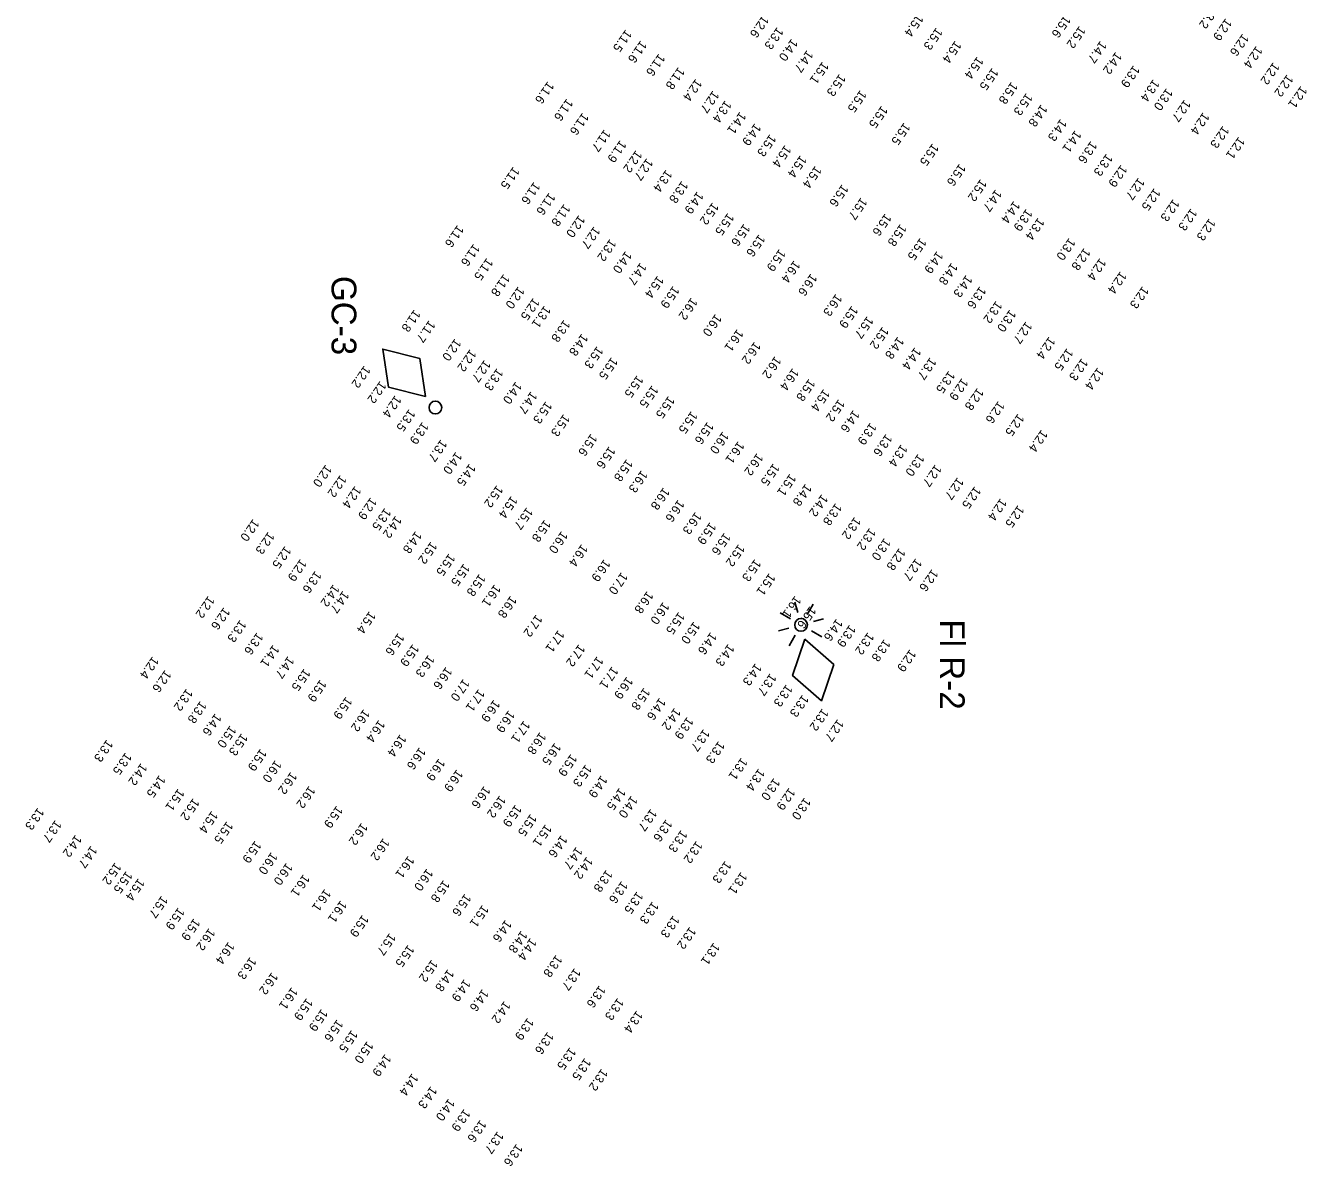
# Model space of a CAD drawing. Extents: x 815385 to 820851, y 582449 to 604245.
# Drawn here: x 815385 to 816108, y 582449 to 583093 of the extents above; entities that cross this region are included whole.
import ezdxf

# ---------------------------------------------------------------- set-up
doc = ezdxf.new("R2010")
doc.units = 0
for name, color, linetype in [('V-CHAN-AIDS', 7, 'Continuous'), ('V-TOPO-SOUN-101408', 7, 'Continuous'), ('V-TOPO-SOUN-EXCSS', 7, 'Continuous')]:
    doc.layers.add(name, color=color, linetype=linetype)

msp = doc.modelspace()

# ---------------------------------------------------------------- linework, layer by layer
at = {"layer": 'V-CHAN-AIDS'}
for p, q in [((815820.52, 582762.05), (815818.96, 582767.85)), ((815829.17, 582766.86), (815825.77, 582760.98)), ((815810.62, 582761.89), (815816.5, 582758.49)), ((815829.33, 582756.96), (815835.13, 582758.52)), ((815815.43, 582753.24), (815809.63, 582751.68)), ((815818.99, 582749.22), (815815.59, 582743.34)), ((815828.26, 582751.71), (815834.14, 582748.31))]:
    msp.add_line(p, q, dxfattribs=at)
for points in [[(815610.36, 582884.04), (815607.23, 582905.45), (815586.27, 582910.8), (815589.4, 582889.39)], [(815824.55, 582746.99), (815817.62, 582726.49), (815833.87, 582712.21), (815840.8, 582732.71)]]:
    msp.add_lwpolyline(points, close=True, dxfattribs=at)
for centre in [(815615.98, 582877.8), (815822.38, 582755.1)]:
    msp.add_circle(centre, 3.6, dxfattribs=at)

# ---------------------------------------------------------------- texts
for s, p in [('GC-3', (815557.34, 582952.11)), ('Fl R-2', (815900.75, 582758.18))]:
    msp.add_text(s, height=14, rotation=270, dxfattribs=at).set_placement(p)
at = {"layer": 'V-TOPO-SOUN-101408'}
for s, p in [('13.2 ', (816054.23, 583104.6)), ('12.6 ', (815800.69, 583099.47)), ('15.4 ', (815887.89, 583100.1)), ('15.6 ', (815971.04, 583099.51)), ('12.9 ', (816062.08, 583097.84)), ('11.5 ', (815723.37, 583091.48)), ('13.3 ', (815808.89, 583092.87)), ('15.3 ', (815898.72, 583092.62)), ('15.2 ', (815979.46, 583093.52)), ('12.6 ', (816071.65, 583089.16)), ('11.6 ', (815731.82, 583085.31)), ('14.0 ', (815817.01, 583086.34)), ('15.4 ', (815909.36, 583085.17)), ('14.7 ', (815991.35, 583085.14)), ('12.4 ', (816079.35, 583082.25)), ('11.6 ', (815742.07, 583077.88)), ('14.7 ', (815825.73, 583079.86)), ('15.4 ', (815921.83, 583076.27)), ('14.2 ', (816000, 583078.92)), ('11.8 ', (815753.14, 583070.29)), ('15.1 ', (815834.48, 583073.42)), ('15.3 ', (815844.04, 583066.43)), ('15.5 ', (815930.27, 583069.86)), ('13.9 ', (816010.07, 583071.31)), ('12.2 ', (816088.97, 583073.04)), ('11.6 ', (815679.4, 583062.22)), ('12.4 ', (815762.92, 583063.72)), ('15.8 ', (815941.12, 583061.99)), ('13.4 ', (816021.22, 583063.42)), ('12.2 ', (816096.73, 583066.15)), ('12.1 ', (816104.56, 583059.7)), ('11.6 ', (815690.13, 583052.51)), ('12.7 ', (815772.62, 583057.03)), ('15.5 ', (815855.8, 583057.36)), ('15.3 ', (815949.55, 583055.62)), ('13.0 ', (816028.67, 583058.4)), ('12.7 ', (816038.83, 583051.97)), ('13.4 ', (815779.59, 583051.54)), ('14.1 ', (815787.85, 583045.07)), ('15.5 ', (815867.8, 583048.47)), ('14.8 ', (815957.93, 583049.21)), ('12.4 ', (816049.4, 583044.8)), ('11.6 ', (815699.02, 583044.55)), ('14.9 ', (815796.29, 583038.57)), ('15.5 ', (815880.51, 583038.96)), ('14.3 ', (815968.87, 583041.06)), ('11.7 ', (815711.32, 583035.13)), ('15.3 ', (815804.78, 583032.39)), ('14.1 ', (815977.09, 583034.67)), ('12.3 ', (816060.53, 583037.14)), ('12.1 ', (816069.43, 583030.98)), ('11.9 ', (815720.23, 583029.03)), ('12.2 ', (815729.16, 583023.35)), ('15.4 ', (815813.29, 583026.27)), ('15.5 ', (815896.58, 583027.21)), ('13.6 ', (815985.96, 583028.55)), ('12.7 ', (815735.27, 583018.87)), ('15.4 ', (815821.99, 583020.52)), ('15.6 ', (815911.83, 583015.8)), ('13.3 ', (815994.75, 583021.4)), ('11.5 ', (815659.93, 583014.05)), ('13.4 ', (815746.14, 583012.37)), ('15.4 ', (815830.43, 583014.57)), ('12.9 ', (816002.99, 583015.15)), ('11.6 ', (815671.62, 583005.49)), ('13.8 ', (815755.08, 583006.08)), ('15.6 ', (815845.56, 583004.09)), ('15.2 ', (815923.7, 583007.08)), ('14.7 ', (815932.19, 583001.25)), ('12.7 ', (816012.82, 583007.88)), ('12.5 ', (816021.75, 583001.94)), ('11.6 ', (815680.14, 582999.38)), ('14.9 ', (815763.76, 583000.06)), ('15.7 ', (815856.23, 582996.66)), ('14.4 ', (815942.48, 582994.74)), ('12.3 ', (816032.46, 582995.8)), ('11.8 ', (815688.6, 582993.02)), ('12.0 ', (815696.93, 582986.73)), ('15.2 ', (815772.4, 582993.89)), ('15.5 ', (815781.02, 582987.92)), ('15.6 ', (815869.87, 582987.64)), ('13.9 ', (815949.5, 582990.27)), ('12.3 ', (816042.49, 582990.56)), ('11.6 ', (815628.46, 582981.17)), ('12.7 ', (815705.49, 582980.36)), ('15.6 ', (815790.12, 582981.84)), ('15.8 ', (815878.41, 582981.75)), ('13.4 ', (815956.22, 582985.29)), ('12.3 ', (816052.83, 582984.92)), ('13.2 ', (815714.52, 582973.29)), ('15.6 ', (815798.61, 582975.88)), ('15.5 ', (815889.66, 582973.88)), ('13.0 ', (815973.69, 582973.83)), ('11.6 ', (815637.55, 582970.53)), ('14.0 ', (815723.31, 582966.47)), ('15.9 ', (815810.11, 582967.58)), ('14.9 ', (815899.1, 582966.4)), ('12.8 ', (815982.2, 582968.19)), ('11.5 ', (815644.96, 582962.52)), ('14.7 ', (815731.64, 582959.93)), ('16.4 ', (815818.41, 582961.15)), ('14.8 ', (815907.3, 582959.87)), ('12.4 ', (815991.07, 582962.47)), ('11.8 ', (815654.5, 582953.45)), ('15.4 ', (815741.37, 582952.53)), ('16.6 ', (815827.91, 582953.74)), ('14.3 ', (815915.55, 582952.92)), ('12.4 ', (816002.64, 582954.97)), ('12.0 ', (815662.73, 582946.46)), ('15.9 ', (815750.16, 582946.76)), ('13.6 ', (815923.31, 582946.54)), ('12.3 ', (816015.16, 582946.58)), ('12.5 ', (815671.26, 582940.04)), ('16.2 ', (815760.39, 582940.15)), ('16.3 ', (815842.04, 582942.28)), ('13.2 ', (815932.45, 582938.3)), ('11.8 ', (815604.02, 582933.4)), ('13.1 ', (815677.52, 582935.66)), ('16.0 ', (815774.04, 582930.9)), ('15.9 ', (815851, 582935.51)), ('15.7 ', (815859.7, 582929.65)), ('13.0 ', (815940.2, 582933.39)), ('11.7 ', (815612.38, 582927.37)), ('13.8 ', (815688.52, 582927.62)), ('16.1 ', (815786.32, 582922.36)), ('15.2 ', (815868.37, 582923.71)), ('12.7 ', (815949.34, 582926.69)), ('12.0 ', (815627, 582917.03)), ('14.8 ', (815698.61, 582919.85)), ('16.2 ', (815796.1, 582915.29)), ('14.8 ', (815876.96, 582918.09)), ('12.4 ', (815962.37, 582918.11)), ('12.2 ', (815635.51, 582910.99)), ('15.3 ', (815707.21, 582912.72)), ('14.4 ', (815886.58, 582912.07)), ('12.5 ', (815972.51, 582911.58)), ('12.2 ', (815575.79, 582901.78)), ('12.7 ', (815643.63, 582904.98)), ('13.3 ', (815650.73, 582900.28)), ('15.5 ', (815715.36, 582906.53)), ('16.2 ', (815807.68, 582907.08)), ('16.4 ', (815817.64, 582900.34)), ('13.7 ', (815895.22, 582906.39)), ('12.3 ', (815980.83, 582905.93)), ('12.4 ', (815989.82, 582900.72)), ('12.2 ', (815584.72, 582893.06)), ('15.5 ', (815729.84, 582896.32)), ('15.8 ', (815826.82, 582894.28)), ('13.5 ', (815905.75, 582898.8)), ('12.9 ', (815913.19, 582894.7)), ('14.0 ', (815661.28, 582892.7)), ('14.7 ', (815669.92, 582887.23)), ('15.5 ', (815738.27, 582890.61)), ('15.4 ', (815835.13, 582888.52)), ('12.8 ', (815921.94, 582889.17)), ('12.4 ', (815593.24, 582885.02)), ('15.3 ', (815678.31, 582881.61)), ('15.5 ', (815747.53, 582884.59)), ('15.2 ', (815843.56, 582882.76)), ('12.6 ', (815933.74, 582881.72)), ('13.5 ', (815601.1, 582877.19)), ('15.3 ', (815688.34, 582874.39)), ('15.5 ', (815760.41, 582876.02)), ('14.6 ', (815851.87, 582876.66)), ('12.5 ', (815944.82, 582874.59)), ('13.9 ', (815608.6, 582869.93)), ('15.6 ', (815769.52, 582869.99)), ('16.0 ', (815778.14, 582864.52)), ('13.9 ', (815861.46, 582869.56)), ('12.4 ', (815958.07, 582865.57)), ('13.7 ', (815619.04, 582860.07)), ('15.6 ', (815703.78, 582863.3)), ('16.1 ', (815786.87, 582859.07)), ('13.6 ', (815870.34, 582863.18)), ('13.4 ', (815878.94, 582857.33)), ('14.0 ', (815627.5, 582853.07)), ('15.6 ', (815714.04, 582856.16)), ('16.2 ', (815797.5, 582852.32)), ('13.0 ', (815888.45, 582851.92)), ('12.0 ', (815554.01, 582845.84)), ('14.5 ', (815635.18, 582846.44)), ('15.8 ', (815723.89, 582848.95)), ('16.3 ', (815732.22, 582842.66)), ('15.5 ', (815806.72, 582846.58)), ('12.7 ', (815898.16, 582845.94)), ('12.2 ', (815562.27, 582840.05)), ('15.1 ', (815816.06, 582840.68)), ('14.8 ', (815824.86, 582835.04)), ('12.7 ', (815910.69, 582838.65)), ('12.4 ', (815570.57, 582833.83)), ('15.2 ', (815650.62, 582834.24)), ('15.4 ', (815658.8, 582828.19)), ('16.8 ', (815744.68, 582832.94)), ('14.2 ', (815834.05, 582829.15)), ('12.5 ', (815920.42, 582833.63)), ('12.9 ', (815579.4, 582827.39)), ('13.5 ', (815587.38, 582821.36)), ('15.7 ', (815667.5, 582821.74)), ('16.6 ', (815753, 582826.08)), ('13.8 ', (815841.88, 582824.11)), ('12.4 ', (815935, 582826.86)), ('12.5 ', (815944.85, 582822.97)), ('12.0 ', (815513.01, 582815.19)), ('14.2 ', (815593.45, 582816.97)), ('15.8 ', (815677.58, 582814.78)), ('16.3 ', (815762.72, 582819.11)), ('15.9 ', (815770.93, 582813.32)), ('13.2 ', (815852.6, 582816.33)), ('12.3 ', (815521.59, 582807.92)), ('14.8 ', (815604.76, 582808.32)), ('16.0 ', (815687.17, 582808.34)), ('15.6 ', (815779.08, 582807.4)), ('13.2 ', (815861.07, 582810.11)), ('12.5 ', (815531.03, 582799.88)), ('15.2 ', (815613.41, 582802.39)), ('16.4 ', (815698.48, 582800.94)), ('15.2 ', (815787.1, 582800.92)), ('13.0 ', (815869.4, 582804.36)), ('12.8 ', (815877.79, 582798.77)), ('12.9 ', (815539.73, 582792.57)), ('15.5 ', (815623.6, 582795.66)), ('16.9 ', (815711.19, 582792.45)), ('15.3 ', (815796.25, 582792.51)), ('12.7 ', (815887.11, 582792.94)), ('13.6 ', (815548.14, 582785.9)), ('15.5 ', (815631.93, 582789.96)), ('17.0 ', (815720.96, 582785.13)), ('15.1 ', (815804.39, 582784.59)), ('12.6 ', (815896.28, 582786.85)), ('14.2 ', (815558.31, 582778.26)), ('15.8 ', (815640.75, 582784.17)), ('16.1 ', (815649.34, 582778.23)), ('12.2 ', (815487.76, 582771.79)), ('14.7 ', (815563.74, 582774.63)), ('16.8 ', (815658.37, 582771.83)), ('16.8 ', (815735.47, 582774.42)), ('12.6 ', (815496.51, 582765.25)), ('15.4 ', (815578.7, 582763.11)), ('16.0 ', (815744.5, 582768.27)), ('15.5 ', (815753.29, 582762.68)), ('13.3 ', (815505.68, 582758.19)), ('17.2 ', (815672.84, 582761.23)), ('15.0 ', (815761.83, 582757.27)), ('14.6 ', (815842.37, 582758.88)), ('13.9 ', (815849.76, 582755.43)), ('13.6 ', (815515.23, 582751.11)), ('15.6 ', (815594.91, 582750.75)), ('17.1 ', (815685.29, 582752.48)), ('14.6 ', (815771.32, 582751.25)), ('13.2 ', (815860.05, 582751.12)), ('14.1 ', (815524.32, 582744.16)), ('15.9 ', (815603.18, 582744.52)), ('17.2 ', (815696.92, 582744.45)), ('14.3 ', (815781.25, 582744.64)), ('13.8 ', (815869.33, 582747.27)), ('12.9 ', (815883.77, 582741.52)), ('12.4 ', (815456.3, 582737.58)), ('14.7 ', (815532.73, 582737.7)), ('16.3 ', (815611.96, 582738.45)), ('17.1 ', (815707.26, 582737.66)), ('14.3 ', (815796.6, 582733.71)), ('12.6 ', (815463.34, 582729.94)), ('15.5 ', (815541.87, 582730.7)), ('16.6 ', (815621.92, 582731.66)), ('17.1 ', (815715.69, 582731.91)), ('13.7 ', (815804.94, 582728.01)), ('13.2 ', (815475.45, 582719.41)), ('15.9 ', (815550.94, 582724.51)), ('17.0 ', (815631.74, 582724.92)), ('16.9 ', (815723.98, 582726.12)), ('15.8 ', (815733.68, 582719.9)), ('13.3 ', (815814.07, 582721.77)), ('13.8 ', (815483.23, 582712.4)), ('15.9 ', (815565.48, 582714.79)), ('17.1 ', (815640.29, 582719.1)), ('16.9 ', (815648.91, 582713.13)), ('14.6 ', (815742.5, 582714.23)), ('13.3 ', (815823.19, 582715.97)), ('14.6 ', (815491.66, 582705.4)), ('16.2 ', (815575.46, 582707.77)), ('16.9 ', (815657.3, 582707.15)), ('14.2 ', (815750.94, 582708.54)), ('13.2 ', (815834.38, 582708.16)), ('15.0 ', (815500.03, 582698.54)), ('16.4 ', (815583.99, 582701.71)), ('17.1 ', (815665.88, 582701.34)), ('13.9 ', (815758.1, 582703.42)), ('12.7 ', (815843.02, 582702.13)), ('13.3 ', (815430.43, 582690.63)), ('15.3 ', (815506.52, 582694.14)), ('16.4 ', (815596.05, 582693.58)), ('16.8 ', (815674.97, 582694.84)), ('13.7 ', (815767.32, 582696.56)), ('13.5 ', (815440.99, 582683.32)), ('15.9 ', (815517.18, 582685.46)), ('16.6 ', (815606.99, 582686.29)), ('16.5 ', (815683.34, 582688.82)), ('13.3 ', (815775.8, 582689.77)), ('14.2 ', (815449.76, 582677.32)), ('16.0 ', (815525.57, 582678.99)), ('16.9 ', (815617.89, 582679.94)), ('15.9 ', (815692.41, 582682.46)), ('15.3 ', (815700.75, 582676.55)), ('13.1 ', (815788.64, 582680.42)), ('14.5 ', (815460.07, 582670.53)), ('16.2 ', (815534.31, 582672.38)), ('16.9 ', (815628, 582673.78)), ('14.9 ', (815709.52, 582670.37)), ('13.4 ', (815798.41, 582674.28)), ('13.0 ', (815807.01, 582668.9)), ('15.1 ', (815470.74, 582662.96)), ('16.2 ', (815544.64, 582664.48)), ('16.6 ', (815643.48, 582664.43)), ('14.5 ', (815719.83, 582663.4)), ('12.9 ', (815815.59, 582663.41)), ('15.2 ', (815479.21, 582657.55)), ('16.2 ', (815652.24, 582659.05)), ('14.0 ', (815726.55, 582658.94)), ('13.0 ', (815824.33, 582657.91)), ('13.3 ', (815391.54, 582652.21)), ('15.4 ', (815489.68, 582650.36)), ('15.9 ', (815560.18, 582653.27)), ('15.9 ', (815661.13, 582653.88)), ('15.5 ', (815669.67, 582648.65)), ('13.7 ', (815737.51, 582651.53)), ('13.7 ', (815401.37, 582645.18)), ('15.5 ', (815498.18, 582644.45)), ('16.2 ', (815574.24, 582643.62)), ('15.1 ', (815678.12, 582642.81)), ('13.6 ', (815746.17, 582645.59)), ('14.2 ', (815412.76, 582636.87)), ('15.9 ', (815514.15, 582633.52)), ('16.2 ', (815586.54, 582634.94)), ('14.6 ', (815686.93, 582636.66)), ('13.3 ', (815754.69, 582639.57)), ('13.2 ', (815763.27, 582633.4)), ('14.7 ', (815421.52, 582630.69)), ('16.0 ', (815523.31, 582627.04)), ('14.7 ', (815695.48, 582630.08)), ('15.2 ', (815435.12, 582621.23)), ('16.0 ', (815531.83, 582621.05)), ('16.1 ', (815600.57, 582624.98)), ('14.2 ', (815701.35, 582624.5)), ('13.3 ', (815779.53, 582622.13)), ('15.5 ', (815441.42, 582616.42)), ('15.4 ', (815448.26, 582612.29)), ('16.1 ', (815541.47, 582614.57)), ('16.0 ', (815611.12, 582617.8)), ('15.8 ', (815620.51, 582611.28)), ('13.8 ', (815712.43, 582617.11)), ('13.6 ', (815721.07, 582610.74)), ('13.1 ', (815788.47, 582615.85)), ('16.1 ', (815553.48, 582606.27)), ('15.6 ', (815632.61, 582603.6)), ('13.5 ', (815729.76, 582604.86)), ('15.7 ', (815461.38, 582602.5)), ('16.1 ', (815562.46, 582599.85)), ('15.1 ', (815642.52, 582597.27)), ('13.3 ', (815738.47, 582599.19)), ('15.9 ', (815470.81, 582595.83)), ('15.9 ', (815479.64, 582589.71)), ('15.9 ', (815574.77, 582591.71)), ('13.3 ', (815750.23, 582591.33)), ('16.2 ', (815488.11, 582584.13)), ('14.6 ', (815655.48, 582588.9)), ('14.8 ', (815664.4, 582582.73)), ('13.2 ', (815759.54, 582584.93)), ('16.4 ', (815499.08, 582576.38)), ('15.7 ', (815590.09, 582581.39)), ('15.5 ', (815600.53, 582574.77)), ('14.4 ', (815669.57, 582578.61)), ('13.1 ', (815773.03, 582575.96)), ('16.3 ', (815511.37, 582567.85)), ('13.8 ', (815684.07, 582569.08)), ('15.2 ', (815613.83, 582566.4)), ('14.8 ', (815622.99, 582561)), ('13.7 ', (815694.5, 582561.61)), ('16.2 ', (815523.6, 582559.25)), ('14.9 ', (815632.26, 582555.34)), ('16.1 ', (815534.81, 582550.81)), ('14.6 ', (815642.47, 582549.74)), ('13.6 ', (815708.49, 582551.86)), ('15.9 ', (815543.24, 582544.66)), ('15.9 ', (815551.64, 582538.52)), ('14.2 ', (815654.86, 582543.05)), ('13.3 ', (815718.84, 582544.78)), ('15.6 ', (815560.42, 582532.6)), ('13.9 ', (815668, 582533.53)), ('13.4 ', (815729.57, 582537.63)), ('15.5 ', (815568.6, 582526.63)), ('13.6 ', (815679.3, 582525.6)), ('15.0 ', (815577.43, 582520.36)), ('13.5 ', (815691.8, 582516.83)), ('14.9 ', (815587.5, 582513.06)), ('13.5 ', (815700.28, 582510.87)), ('13.2 ', (815709.77, 582504.88)), ('14.4 ', (815602.78, 582502.16)), ('14.3 ', (815613.37, 582494.93)), ('14.0 ', (815623.39, 582487.95)), ('13.9 ', (815632.14, 582482.03)), ('13.6 ', (815641.21, 582475.92)), ('13.7 ', (815651, 582469.39)), ('13.6 ', (815661.74, 582462.36))]:
    msp.add_text(s, height=5, rotation=234.911, dxfattribs=at).set_placement(p)
at = {"layer": 'V-TOPO-SOUN-EXCSS'}
for s, p in [('16.1 ', (815818.97, 582771.83)), ('15.6 ', (815827.36, 582765.91))]:
    msp.add_text(s, height=5, rotation=234.911, dxfattribs=at).set_placement(p)

doc.saveas('drawing.dxf')
